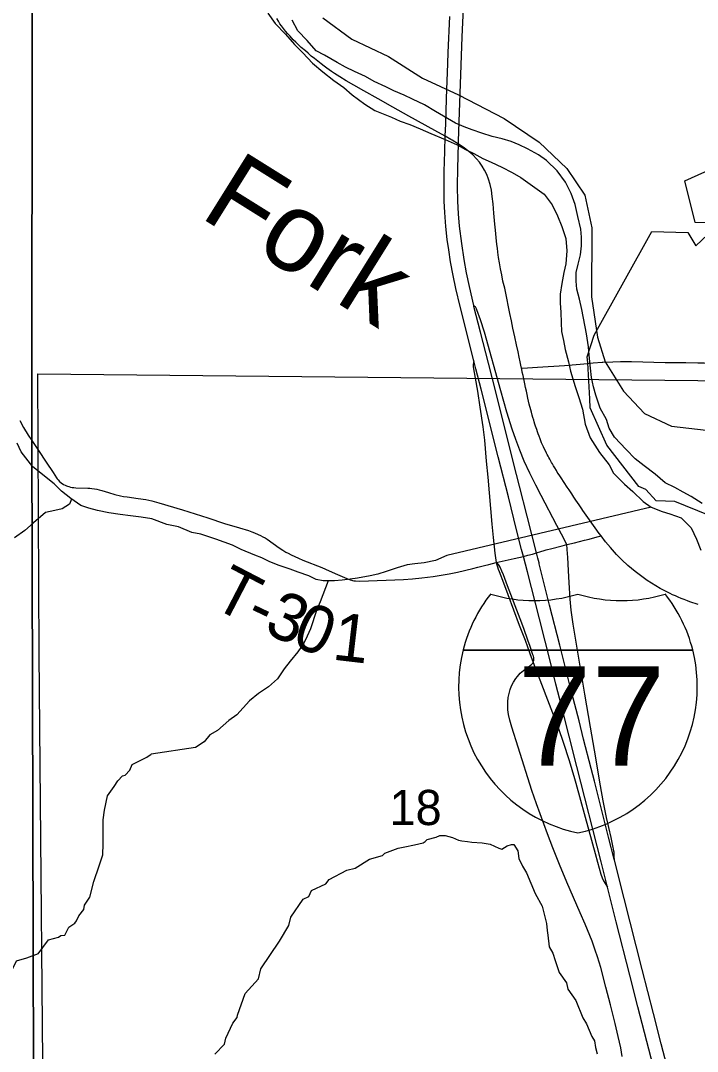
# Model space of a CAD drawing. Extents: x 0 to 34, y 0 to 22.
# Drawn here: x 4.535 to 5.34, y 15.855 to 17.081 of the extents above; entities that cross this region are included whole.
import ezdxf

# ---------------------------------------------------------------- set-up
doc = ezdxf.new("R2010")
doc.units = 0
for name, color, linetype in [('GM_X_Corporation', 7, 'Continuous'), ('GM_X_County_Road', 7, 'Continuous'), ('GM_X_Interchange_Ramps', 7, 'Continuous'), ('GM_X_Interstate_Location', 7, 'Continuous'), ('GM_X_Interstate_Route', 7, 'Continuous'), ('GM_X_Interstate_Shield', 7, 'Continuous'), ('GM_X_Major_River', 7, 'Continuous'), ('GM_X_Major_River_Text', 7, 'Continuous'), ('GM_X_Minor_River', 7, 'Continuous'), ('GM_X_Rail_Line', 7, 'Continuous'), ('GM_X_Section', 7, 'Continuous'), ('GM_X_Section_Text', 7, 'Continuous'), ('GM_X_State_Route', 7, 'Continuous'), ('GM_X_Township_Road', 7, 'Continuous'), ('GM_X_Township_Road_Text', 7, 'Continuous'), ('SH_Cut_Line', 7, 'Continuous')]:
    doc.layers.add(name, color=color, linetype=linetype)

msp = doc.modelspace()

# ---------------------------------------------------------------- linework, layer by layer
at = {"layer": 'GM_X_Corporation'}
msp.add_lwpolyline([(5.3537, 16.4929), (5.3136, 16.509), (5.2913, 16.5099), (5.2788, 16.5233), (5.2708, 16.5268), (5.2324, 16.5759), (5.2128, 16.6205), (5.2122, 16.631), (5.2098, 16.674), (5.2092, 16.6811), (5.2173, 16.707), (5.2859, 16.8301), (5.3288, 16.8292), (5.3386, 16.8131), (5.367, 16.8401), (5.3377, 16.8408), (5.3252, 16.8907), (5.3811, 16.9157)], dxfattribs=at)
at = {"layer": 'GM_X_County_Road'}
for points in [[(5.185, 16.4577), (5.1939, 16.4599), (5.2059, 16.4629), (5.2113, 16.4643), (5.2209, 16.4668), (5.2257, 16.4681)], [(5.1006, 16.4366), (5.1223, 16.4411), (5.1277, 16.4423), (5.1332, 16.4437), (5.1385, 16.4451), (5.1439, 16.4465), (5.1488, 16.4479), (5.1539, 16.4494), (5.1579, 16.4507), (5.1603, 16.4513), (5.162, 16.4518), (5.1656, 16.4527), (5.1794, 16.4563), (5.185, 16.4577)], [(5.145, 16.3173), (5.1454, 16.3189), (5.1456, 16.3202), (5.1457, 16.3212), (5.1457, 16.3223), (5.1455, 16.3235), (5.1452, 16.3248), (5.1446, 16.3267), (5.1412, 16.3364), (5.1386, 16.3439), (5.1338, 16.3577), (5.1293, 16.3693), (5.1144, 16.4088), (5.1094, 16.4219), (5.1076, 16.4263), (5.1056, 16.431), (5.1045, 16.433), (5.1037, 16.4342), (5.1025, 16.4353), (5.1006, 16.4366)], [(5.2507, 15.8485), (5.249, 15.8589), (5.2462, 15.8723), (5.2425, 15.8879), (5.2367, 15.9102), (5.2313, 15.9313), (5.2252, 15.9547), (5.2215, 15.9671), (5.2188, 15.9753), (5.2149, 15.9858), (5.2066, 16.0059), (5.2008, 16.0196), (5.185, 16.0561), (5.176, 16.0772), (5.1682, 16.0968), (5.1618, 16.1137), (5.1487, 16.1493), (5.1432, 16.1651), (5.1269, 16.2167), (5.1194, 16.2404), (5.1171, 16.2488), (5.1156, 16.2556), (5.1148, 16.2612), (5.1145, 16.2656), (5.1145, 16.2706), (5.1151, 16.2757), (5.1161, 16.2806), (5.1175, 16.2855), (5.1192, 16.2896), (5.1214, 16.2941), (5.1242, 16.2984), (5.1261, 16.3009), (5.1295, 16.3046), (5.1333, 16.308), (5.1348, 16.3092), (5.137, 16.3109), (5.1388, 16.3121), (5.1403, 16.3132), (5.1418, 16.3142), (5.1429, 16.3151), (5.1438, 16.3158), (5.1445, 16.3165), (5.145, 16.3173)]]:
    msp.add_lwpolyline(points, dxfattribs=at)
at = {"layer": 'GM_X_Interchange_Ramps'}
for points in [[(5.185, 16.4577), (5.1784, 16.4703), (5.173, 16.4805), (5.1542, 16.5162), (5.1479, 16.5283), (5.1408, 16.5428), (5.1343, 16.557), (5.1288, 16.5701), (5.124, 16.5829), (5.1197, 16.5952), (5.1135, 16.6154), (5.1063, 16.6405), (5.0868, 16.7105), (5.082, 16.7253), (5.0779, 16.7371), (5.0775, 16.7382), (5.077, 16.739), (5.0765, 16.7398), (5.076, 16.7405), (5.0755, 16.741), (5.075, 16.7416), (5.074, 16.7424)], [(5.0743, 16.6763), (5.0738, 16.6749), (5.0736, 16.6738), (5.0734, 16.6725), (5.0733, 16.6714), (5.0732, 16.6703), (5.0733, 16.6692), (5.0756, 16.6556), (5.0785, 16.6404), (5.0815, 16.6213), (5.0847, 16.5979), (5.0867, 16.5818), (5.089, 16.5571), (5.0907, 16.5379), (5.0958, 16.4821), (5.0973, 16.466), (5.0993, 16.4475), (5.1006, 16.4366)], [(5.2415, 16.0824), (5.2414, 16.0865), (5.2413, 16.0884), (5.2413, 16.0899), (5.2411, 16.0916), (5.2409, 16.0929), (5.2405, 16.0956), (5.2402, 16.0975), (5.2375, 16.1094), (5.2322, 16.1329), (5.228, 16.153), (5.2249, 16.1707), (5.218, 16.2131), (5.2132, 16.2406), (5.2063, 16.2797), (5.1925, 16.363), (5.1902, 16.3796), (5.189, 16.3926), (5.1876, 16.4125), (5.1869, 16.4267), (5.186, 16.4429), (5.1858, 16.4466), (5.185, 16.4577)], [(5.1006, 16.4366), (5.1016, 16.4335), (5.1023, 16.4312), (5.1032, 16.4284), (5.1042, 16.4257), (5.1094, 16.4124), (5.1146, 16.3985), (5.1283, 16.3619), (5.1351, 16.3439), (5.1409, 16.3282), (5.145, 16.3173), (5.1547, 16.2917), (5.1618, 16.2731), (5.1748, 16.2389), (5.1807, 16.2226), (5.1878, 16.2007), (5.194, 16.1793), (5.1955, 16.1739), (5.211, 16.1176), (5.2185, 16.0901), (5.2213, 16.0799), (5.2253, 16.0655), (5.2268, 16.0612), (5.2287, 16.0576), (5.2332, 16.05)]]:
    msp.add_lwpolyline(points, dxfattribs=at)
at = {"layer": 'GM_X_Interstate_Route'}
msp.add_line((5.152, 16.435), (5.1518, 16.4359), dxfattribs=at)
for points in [[(5.2332, 16.05), (5.2256, 16.0804), (5.197, 16.1936), (5.1785, 16.2658), (5.1719, 16.2917), (5.1678, 16.3079), (5.1657, 16.3164), (5.1524, 16.3694), (5.1379, 16.4253), (5.1332, 16.4437), (5.131, 16.452), (5.1251, 16.4752), (5.1153, 16.5144), (5.1033, 16.562), (5.0828, 16.6427), (5.0767, 16.6668), (5.0743, 16.6763), (5.058, 16.7409), (5.0528, 16.7626), (5.0496, 16.7778), (5.0465, 16.7943), (5.0443, 16.8084), (5.0426, 16.8207), (5.041, 16.8361), (5.0396, 16.8528), (5.039, 16.8664), (5.0387, 16.8838), (5.0389, 16.9018), (5.0395, 16.9253), (5.0402, 16.9435), (5.0407, 16.9582), (5.0413, 16.9731), (5.0417, 16.9887), (5.0432, 17.0302), (5.0438, 17.0433), (5.0455, 17.0861)], [(5.0555, 16.9233), (5.0558, 16.9316), (5.0558, 16.9341), (5.056, 16.9378), (5.0567, 16.9608), (5.0604, 17.0619), (5.0617, 17.0961)], [(5.1495, 16.4448), (5.1488, 16.4479), (5.1378, 16.4917), (5.1286, 16.5272), (5.1214, 16.5549), (5.1006, 16.6381), (5.0915, 16.6736), (5.082, 16.7103), (5.0743, 16.741), (5.074, 16.7424), (5.0689, 16.7647), (5.0655, 16.7811), (5.0625, 16.797), (5.0597, 16.8161), (5.0573, 16.8365), (5.056, 16.8514), (5.0551, 16.8663), (5.0547, 16.8837), (5.055, 16.9061), (5.0554, 16.9192), (5.0555, 16.9233)], [(5.1518, 16.4359), (5.1503, 16.4417), (5.1495, 16.4448)], [(5.2415, 16.0824), (5.2412, 16.0836), (5.2347, 16.1095), (5.2177, 16.1763), (5.2138, 16.1913), (5.2049, 16.2262), (5.1995, 16.2479), (5.1909, 16.281), (5.1764, 16.3381), (5.1643, 16.3857), (5.152, 16.435)], [(5.3041, 15.8381), (5.2974, 15.8639), (5.2879, 15.9), (5.2745, 15.9523), (5.253, 16.0366), (5.2415, 16.0824)], [(5.2984, 15.7964), (5.2695, 15.9076), (5.2598, 15.9455), (5.2437, 16.009), (5.2332, 16.05)]]:
    msp.add_lwpolyline(points, dxfattribs=at)
at = {"layer": 'GM_X_Interstate_Shield'}
for p, q in [((5.0615, 16.3323), (5.3347, 16.3323)), ((5.3347, 16.3323), (5.0615, 16.3323)), ((5.3347, 16.3323), (5.0615, 16.3323))]:
    msp.add_line(p, q, dxfattribs=at)
for centre, start, end in [((5.2336, 16.2888), 141.669, 165.8066), ((5.1462, 16.5687), 253.0091, 286.9909), ((5.25, 16.5687), 253.0091, 286.9909), ((5.1626, 16.2888), 14.1934, 38.331), ((5.2336, 16.2888), 165.8066, 258.463), ((5.1626, 16.2888), 281.537, 14.1934)]:
    msp.add_arc(centre, 0.1776, start, end, dxfattribs=at)
at = {"layer": 'GM_X_Major_River'}
for points in [[(4.829, 17.0901), (4.8378, 17.0777), (4.8501, 17.0649), (4.8605, 17.0528), (4.8708, 17.0427), (4.8823, 17.0307), (4.8945, 17.0202), (4.9075, 17.01), (4.9194, 17.0018), (4.9293, 16.9928), (4.9446, 16.9819), (4.9565, 16.9744), (4.9763, 16.9663), (4.9866, 16.9614), (4.998, 16.9577), (5.0102, 16.9525), (5.0228, 16.9469), (5.0399, 16.9399), (5.0544, 16.9332), (5.0643, 16.928), (5.0742, 16.9231), (5.0849, 16.9172), (5.0948, 16.9127), (5.1074, 16.9067), (5.12, 16.9004), (5.1303, 16.8944), (5.1441, 16.8847), (5.1578, 16.8746), (5.1674, 16.8621), (5.1736, 16.8489), (5.1791, 16.8364), (5.1837, 16.8221), (5.185, 16.8073), (5.1836, 16.7917), (5.1814, 16.7815), (5.1789, 16.7685), (5.1771, 16.7556), (5.1768, 16.745), (5.1777, 16.7344), (5.1782, 16.7215), (5.1786, 16.7113), (5.181, 16.7007), (5.183, 16.6897), (5.1869, 16.6753), (5.1893, 16.6639), (5.1948, 16.6458), (5.1991, 16.6329), (5.2034, 16.6189), (5.2069, 16.6011), (5.2128, 16.5849), (5.2239, 16.5675), (5.2351, 16.5528), (5.2405, 16.5426), (5.2535, 16.5298)], [(5.2662, 16.5599), (5.2554, 16.5708), (5.2416, 16.5855), (5.2351, 16.5964), (5.232, 16.6067), (5.2246, 16.6202), (5.2196, 16.6354), (5.2168, 16.6456), (5.2144, 16.6566), (5.2132, 16.6676), (5.2115, 16.6831), (5.2107, 16.693), (5.2083, 16.7085), (5.2027, 16.7373), (5.1999, 16.7498), (5.1968, 16.7615), (5.196, 16.771), (5.1962, 16.7816), (5.1984, 16.7915), (5.201, 16.8025), (5.2024, 16.8131), (5.2023, 16.8234), (5.2015, 16.8332), (5.1979, 16.848), (5.1948, 16.8624), (5.1901, 16.8756), (5.1835, 16.8888), (5.1735, 16.9024), (5.1605, 16.9148), (5.151, 16.9215), (5.138, 16.9286), (5.1281, 16.9335), (5.1186, 16.9372), (5.1079, 16.9405), (5.0961, 16.9434), (5.0839, 16.9471), (5.0721, 16.9512), (5.0626, 16.9549), (5.0523, 16.959), (5.0286, 16.9732), (5.0153, 16.981), (5.0012, 16.9877), (4.9912, 16.9926), (4.979, 16.9978), (4.9695, 17.0022), (4.9554, 17.0089), (4.9451, 17.0145), (4.9321, 17.0205), (4.9215, 17.0257), (4.9115, 17.0313), (4.8963, 17.0399), (4.8864, 17.0451), (4.8756, 17.0575), (4.8645, 17.0692), (4.8579, 17.0817)], [(5.346, 16.5068), (5.333, 16.515), (5.3235, 16.5202), (5.3136, 16.5255), (5.3021, 16.5314), (5.2899, 16.5416), (5.2769, 16.5513), (5.2662, 16.5599)], [(5.2535, 16.5298), (5.2635, 16.5208), (5.2757, 16.5092), (5.2853, 16.5021), (5.2982, 16.4972), (5.3077, 16.4943), (5.3211, 16.4895), (5.333, 16.4778), (5.3392, 16.4642), (5.3446, 16.451)]]:
    msp.add_lwpolyline(points, dxfattribs=at)
at = {"layer": 'GM_X_Minor_River'}
for points in [[(4.5491, 16.5501), (4.5353, 16.5682), (4.5306, 16.5784)], [(5.2853, 16.5021), (5.0422, 16.4448), (5.0286, 16.4389), (5.015, 16.436), (5.004, 16.4347), (4.9949, 16.4335), (4.9831, 16.4302), (4.9699, 16.4259), (4.9597, 16.4227), (4.9506, 16.4206), (4.9358, 16.4178), (4.9271, 16.4165), (4.9176, 16.4156), (4.9085, 16.4147), (4.8948, 16.4145), (4.8864, 16.4163), (4.8776, 16.4207), (4.865, 16.425), (4.8554, 16.4283), (4.8424, 16.4327), (4.8313, 16.4374), (4.8217, 16.4419), (4.8133, 16.4451), (4.7973, 16.4517), (4.7869, 16.4569), (4.767, 16.4642), (4.7491, 16.47), (4.7384, 16.4721), (4.7227, 16.4787), (4.7086, 16.4815), (4.691, 16.4885), (4.6781, 16.4902), (4.6655, 16.4919), (4.6533, 16.4936), (4.6396, 16.4957), (4.6262, 16.4981), (4.6159, 16.501), (4.6064, 16.5043), (4.5945, 16.5124), (4.5833, 16.5214), (4.5744, 16.53), (4.5491, 16.5501)], [(4.5952, 16.5119), (4.5927, 16.506), (4.584, 16.5001), (4.5753, 16.4981), (4.5643, 16.496), (4.5499, 16.4838)], [(4.5499, 16.4838), (4.5397, 16.4746), (4.5272, 16.4658)], [(4.9009, 16.4146), (4.8913, 16.3898), (4.8869, 16.3794), (4.8796, 16.3573), (4.8756, 16.3489), (4.8719, 16.3405), (4.8645, 16.3301), (4.8555, 16.319), (4.8484, 16.3098), (4.8406, 16.2979), (4.8297, 16.2886), (4.818, 16.2804), (4.8071, 16.2719), (4.7922, 16.255), (4.7824, 16.2484), (4.7692, 16.2364), (4.7598, 16.2313), (4.7531, 16.2229), (4.7429, 16.2163), (4.69, 16.2082)], [(4.5556, 15.9709), (4.5678, 15.9874), (4.5799, 15.9907), (4.5825, 15.9926), (4.5871, 15.9931), (4.5922, 16.0026), (4.599, 16.0073), (4.6012, 16.01), (4.6038, 16.0161), (4.6097, 16.0234), (4.6108, 16.0288), (4.6171, 16.0384), (4.6217, 16.0567), (4.6282, 16.0754), (4.6325, 16.0884), (4.633, 16.1017), (4.6328, 16.118), (4.6329, 16.1302), (4.6343, 16.1416), (4.6381, 16.1587), (4.6459, 16.1699), (4.6503, 16.1768), (4.6559, 16.1826), (4.659, 16.1834), (4.6646, 16.1892), (4.6675, 16.1961), (4.6848, 16.2047), (4.69, 16.2082)], [(4.7657, 15.8515), (4.7773, 15.8635), (4.779, 15.8703), (4.7874, 15.8883), (4.7926, 15.8952), (4.793, 15.8979), (4.802, 15.9235), (4.8177, 15.9412), (4.8205, 15.953), (4.8427, 15.9857), (4.8538, 16.0045), (4.8563, 16.0144), (4.8711, 16.0359), (4.8778, 16.039), (4.8811, 16.0463), (4.8981, 16.0542), (4.9018, 16.0592), (4.9229, 16.0702), (4.9331, 16.0726), (4.95, 16.0835), (4.9654, 16.0879), (4.9681, 16.0906), (4.9843, 16.0966), (4.9922, 16.0982), (5.0036, 16.1003), (5.0138, 16.1027), (5.0164, 16.1043), (5.0186, 16.107), (5.0292, 16.1098), (5.0338, 16.1114), (5.0402, 16.1115), (5.0486, 16.1094), (5.0559, 16.1061), (5.06, 16.1054), (5.0665, 16.1043), (5.0718, 16.1037), (5.084, 16.1027), (5.0935, 16.1013), (5.1039, 16.0966), (5.1077, 16.0955), (5.1137, 16.0994), (5.119, 16.101), (5.122, 16.101), (5.1267, 16.0935), (5.1276, 16.0844), (5.1323, 16.075), (5.137, 16.0671), (5.1473, 16.0425), (5.1555, 16.0275), (5.1605, 16.0067), (5.1614, 15.9987), (5.1622, 15.993), (5.164, 15.979), (5.1683, 15.9714), (5.1711, 15.9628), (5.1759, 15.9484), (5.1845, 15.9364), (5.1861, 15.9288), (5.1958, 15.9153), (5.2038, 15.8945), (5.2085, 15.8874), (5.2148, 15.8726), (5.2179, 15.8674), (5.2192, 15.8594), (5.2212, 15.8518)], [(4.5556, 15.9709), (4.5416, 15.9658), (4.5295, 15.9619), (4.5247, 15.9523), (4.5127, 15.9416), (4.5029, 15.9377), (4.4916, 15.9288), (4.48, 15.9192), (4.4653, 15.9111), (4.4525, 15.8988), (4.4389, 15.8914), (4.4265, 15.8837), (4.4148, 15.8794), (4.4009, 15.8743), (4.3869, 15.8662)]]:
    msp.add_lwpolyline(points, dxfattribs=at)
at = {"layer": 'GM_X_Rail_Line'}
msp.add_lwpolyline([(2.1, 18.7171), (2.1, 14.1), (4.5781, 14.1), (4.5658, 14.9668), (4.5509, 15.5331), (4.5478, 16.582), (4.5489, 17.6578), (4.5474, 17.7028), (4.5429, 17.9404), (4.5419, 17.9684), (4.5402, 18.2851), (4.5408, 18.3763), (4.5397, 18.3961), (4.5397, 18.4045), (4.5399, 18.4424), (4.5403, 18.5054), (4.5462, 18.6416), (3.8456, 18.6615), (3.8442, 18.6615), (2.9234, 18.6945), (2.9222, 18.6946), (2.7892, 18.6993), (2.7864, 18.6994)], close=True, dxfattribs=at)
for points in [[(7.149, 16.6283), (5.9824, 16.6436), (5.6594, 16.6485), (5.6614, 16.7344), (5.6628, 16.7878), (5.6628, 16.7899), (5.6656, 16.9939), (5.6743, 17.6274), (5.3403, 17.635), (5.2052, 17.638), (4.9797, 17.6498), (4.9624, 17.6496), (4.8158, 17.6467), (4.5489, 17.6578), (4.5478, 16.582), (4.5509, 15.5331), (4.5658, 14.9668), (4.5781, 14.1), (8.76, 14.1)], [(4.8946, 17.0844), (4.9288, 17.0592), (4.9726, 17.0385), (5.0131, 17.0128), (5.056, 16.9928), (5.1102, 16.9646), (5.1519, 16.9367), (5.185, 16.9052), (5.2062, 16.8735), (5.2148, 16.8347), (5.2142, 16.7524), (5.2213, 16.7044), (5.2304, 16.675), (5.2525, 16.6402), (5.2775, 16.6139), (5.3095, 16.5985), (5.3508, 16.594)]]:
    msp.add_lwpolyline(points, dxfattribs=at)
at = {"layer": 'GM_X_Section'}
msp.add_lwpolyline([(4.555, 16.6608), (5.6553, 16.6499), (5.6397, 15.6496), (4.5625, 15.6671), (4.5568, 16.3278)], close=True, dxfattribs=at)
at = {"layer": 'GM_X_State_Route'}
for points in [[(5.1375, 16.6364), (5.1367, 16.6402), (5.1358, 16.6445), (5.1348, 16.6492), (5.1336, 16.6548), (5.1328, 16.6591), (5.1319, 16.663), (5.1312, 16.6666), (5.131, 16.6675), (5.1303, 16.6711), (5.1294, 16.6751), (5.1281, 16.6809), (5.1268, 16.6869), (5.125, 16.6953), (5.1229, 16.705), (5.1208, 16.7153), (5.1189, 16.7241), (5.1171, 16.7328), (5.1155, 16.7407), (5.1133, 16.7511), (5.1109, 16.7627), (5.1089, 16.7712), (5.1075, 16.7786), (5.1061, 16.7858), (5.1048, 16.793), (5.1037, 16.7995), (5.1028, 16.8058), (5.1022, 16.8103), (5.1017, 16.8149), (5.1008, 16.8231), (5.0998, 16.8318), (5.0992, 16.8391), (5.0981, 16.8521), (5.0972, 16.8633), (5.0962, 16.8721), (5.0951, 16.8794), (5.0935, 16.8861), (5.0915, 16.8927), (5.0895, 16.898), (5.087, 16.9031), (5.0841, 16.908), (5.0808, 16.9126), (5.0772, 16.9169), (5.0728, 16.9214), (5.0681, 16.9256), (5.0631, 16.9294), (5.0603, 16.9313), (5.0558, 16.9341), (5.0482, 16.9388), (5.0467, 16.9397), (5.0402, 16.9435), (5.0278, 16.9506), (4.9968, 16.9676), (4.9779, 16.9783), (4.9601, 16.9882), (4.9433, 16.9976), (4.9315, 17.0043), (4.9223, 17.0096), (4.9145, 17.0143), (4.9083, 17.0181), (4.9046, 17.0206), (4.9018, 17.0225), (4.8991, 17.0245), (4.896, 17.0268), (4.8924, 17.0296), (4.8884, 17.0328), (4.8844, 17.0361), (4.8807, 17.039), (4.8769, 17.0423), (4.8737, 17.0451), (4.8688, 17.0493), (4.8649, 17.0529), (4.8621, 17.0555), (4.8591, 17.0585), (4.8554, 17.0625), (4.8525, 17.0658), (4.8498, 17.0688), (4.8474, 17.072), (4.8452, 17.0749), (4.8434, 17.0775), (4.8415, 17.0806), (4.8395, 17.0837)], [(5.3414, 16.3866), (5.3378, 16.3876), (5.3349, 16.3886), (5.3314, 16.3897), (5.3285, 16.3908), (5.3245, 16.3923), (5.3211, 16.3937), (5.3176, 16.3951), (5.3142, 16.3966), (5.3108, 16.3981), (5.308, 16.3994), (5.3047, 16.401), (5.2998, 16.4036), (5.2962, 16.4056), (5.2909, 16.4087), (5.2806, 16.4152), (5.274, 16.4198), (5.2662, 16.4258), (5.2576, 16.433), (5.2503, 16.4396), (5.2442, 16.4458), (5.2368, 16.4541), (5.2309, 16.4612), (5.2257, 16.4681), (5.2234, 16.4711), (5.2119, 16.4873), (5.204, 16.4984), (5.2026, 16.5004), (5.201, 16.5027), (5.1995, 16.505), (5.1958, 16.5105), (5.1934, 16.5141), (5.1907, 16.5181), (5.1876, 16.5227), (5.1853, 16.5262), (5.1781, 16.5372), (5.1764, 16.5397), (5.1747, 16.5423), (5.1735, 16.5441), (5.1724, 16.5458), (5.1705, 16.549), (5.1691, 16.5513), (5.1677, 16.5537), (5.1666, 16.5555), (5.1657, 16.5571), (5.1645, 16.5593), (5.1635, 16.5612), (5.1626, 16.5631), (5.1616, 16.5648), (5.1607, 16.5666), (5.1598, 16.5684), (5.1585, 16.5712), (5.157, 16.574), (5.1558, 16.5766), (5.1548, 16.579), (5.1539, 16.5811), (5.1531, 16.5834), (5.1518, 16.5867), (5.1508, 16.5894), (5.15, 16.5918), (5.149, 16.5945), (5.1483, 16.5968), (5.1476, 16.5987), (5.1469, 16.601), (5.1462, 16.6036), (5.1455, 16.6058), (5.1446, 16.6088), (5.1437, 16.6119), (5.1428, 16.6152), (5.142, 16.6182), (5.1402, 16.625), (5.1386, 16.6319), (5.1375, 16.6364)]]:
    msp.add_lwpolyline(points, dxfattribs=at)
at = {"layer": 'GM_X_Township_Road'}
for points in [[(5.131, 16.6675), (5.1381, 16.668), (5.1499, 16.6687), (5.182, 16.671), (5.21, 16.6734)], [(5.21, 16.6734), (5.2161, 16.6739), (5.2269, 16.6747), (5.2278, 16.6747)], [(5.2278, 16.6747), (5.2395, 16.6753), (5.2488, 16.6755), (5.2618, 16.6754), (5.302, 16.6745), (5.3267, 16.6742), (5.3409, 16.6739), (5.3484, 16.6739), (5.3651, 16.6737), (5.3726, 16.6737)], [(4.5335, 16.6052), (4.5381, 16.5971), (4.5437, 16.5881), (4.548, 16.5815)], [(4.548, 16.5815), (4.5519, 16.5755), (4.5558, 16.5696), (4.565, 16.5557), (4.5732, 16.5435), (4.5773, 16.5372), (4.5781, 16.536), (4.5792, 16.5346), (4.581, 16.5328), (4.583, 16.5311), (4.5857, 16.5294), (4.5875, 16.5284), (4.5891, 16.5277), (4.5906, 16.5272), (4.5921, 16.5267), (4.594, 16.5262), (4.5959, 16.5257), (4.5979, 16.5255), (4.6002, 16.5253), (4.6145, 16.5248), (4.6171, 16.5247), (4.6194, 16.5244), (4.6225, 16.524), (4.6255, 16.5235), (4.6281, 16.5229), (4.6314, 16.522), (4.6391, 16.5196), (4.6469, 16.5173), (4.6536, 16.5157), (4.6572, 16.5151), (4.6616, 16.5144), (4.6745, 16.5127), (4.6837, 16.5114), (4.6909, 16.5099), (4.6993, 16.5076), (4.7272, 16.499), (4.7574, 16.4894), (4.7775, 16.483), (4.7953, 16.4775), (4.806, 16.4744), (4.8098, 16.4731), (4.813, 16.4719), (4.8175, 16.4699), (4.8204, 16.4685), (4.823, 16.4671), (4.8257, 16.4656), (4.8282, 16.464), (4.8351, 16.459), (4.8423, 16.454), (4.8467, 16.4511), (4.8503, 16.4489), (4.8531, 16.4474), (4.8568, 16.4455), (4.861, 16.4435), (4.8656, 16.4414), (4.8707, 16.4393), (4.8932, 16.4303), (4.9019, 16.4264), (4.912, 16.422), (4.9228, 16.4174), (4.9249, 16.4166), (4.927, 16.4159), (4.9285, 16.4154), (4.9299, 16.415), (4.9315, 16.4148), (4.9332, 16.4146), (4.9383, 16.4144), (4.9905, 16.4162), (5.0011, 16.4169), (5.0122, 16.418), (5.0258, 16.4199), (5.0448, 16.423), (5.0546, 16.425), (5.0728, 16.4293), (5.0791, 16.4309), (5.0867, 16.4328), (5.092, 16.4342), (5.0964, 16.4354), (5.1006, 16.4366)]]:
    msp.add_lwpolyline(points, dxfattribs=at)
at = {"layer": 'SH_Cut_Line'}
for points in [[(2.1, 14.1), (4.5781, 14.1), (4.5658, 14.9668), (4.5509, 15.5331), (4.5478, 16.582), (4.5489, 17.6578), (4.8158, 17.6467), (4.9624, 17.6496), (4.9797, 17.6498), (5.2052, 17.638), (5.3403, 17.635), (5.6743, 17.6274), (5.6656, 16.9939), (5.6628, 16.7899), (5.6628, 16.7878), (5.6614, 16.7344), (5.6594, 16.6485), (5.9824, 16.6436), (7.149, 16.6283)], [(7.149, 16.6283), (5.9824, 16.6436), (5.6594, 16.6485), (5.6614, 16.7344), (5.6628, 16.7878), (5.6628, 16.7899), (5.6656, 16.9939), (5.6743, 17.6274), (5.3403, 17.635), (5.2052, 17.638), (4.9797, 17.6498), (4.9624, 17.6496), (4.8158, 17.6467), (4.5489, 17.6578), (4.5478, 16.582), (4.5509, 15.5331), (4.5658, 14.9668), (4.5781, 14.1), (8.9, 14.1)]]:
    msp.add_lwpolyline(points, dxfattribs=at)

# ---------------------------------------------------------------- texts
at = {"layer": 'GM_X_Interstate_Location'}
for s in ['.', '-', ',']:
    msp.add_text(s, height=0.000189, dxfattribs=at).set_placement((5.1981, 16.2567))
msp.add_text('77', height=0.000189, rotation=0, dxfattribs=at).set_placement((5.1594, 16.2175))
at = {"layer": 'GM_X_Interstate_Shield'}
msp.add_text('77', height=0.11837, dxfattribs=at).set_placement((5.1262, 16.1947))
at = {"layer": 'GM_X_Major_River_Text'}
msp.add_text('Fork', height=0.09469, rotation=328.0028, dxfattribs=at).set_placement((4.7462, 16.8483))
at = {"layer": 'GM_X_Section_Text'}
msp.add_text('18', height=0.04186, rotation=0, dxfattribs=at).set_placement((4.9736, 16.124))
at = {"layer": 'GM_X_Township_Road_Text'}
for s, rotation, p in [('T', 332.5494, (4.7601, 16.385)), ('3', 336.3296, (4.8226, 16.3536)), ('-', 334.585, (4.7998, 16.3644)), ('0', 336.8926, (4.8552, 16.3393)), ('1', 353.3019, (4.9045, 16.3211))]:
    msp.add_text(s, height=0.0568, rotation=rotation, dxfattribs=at).set_placement(p)

doc.saveas('drawing.dxf')
